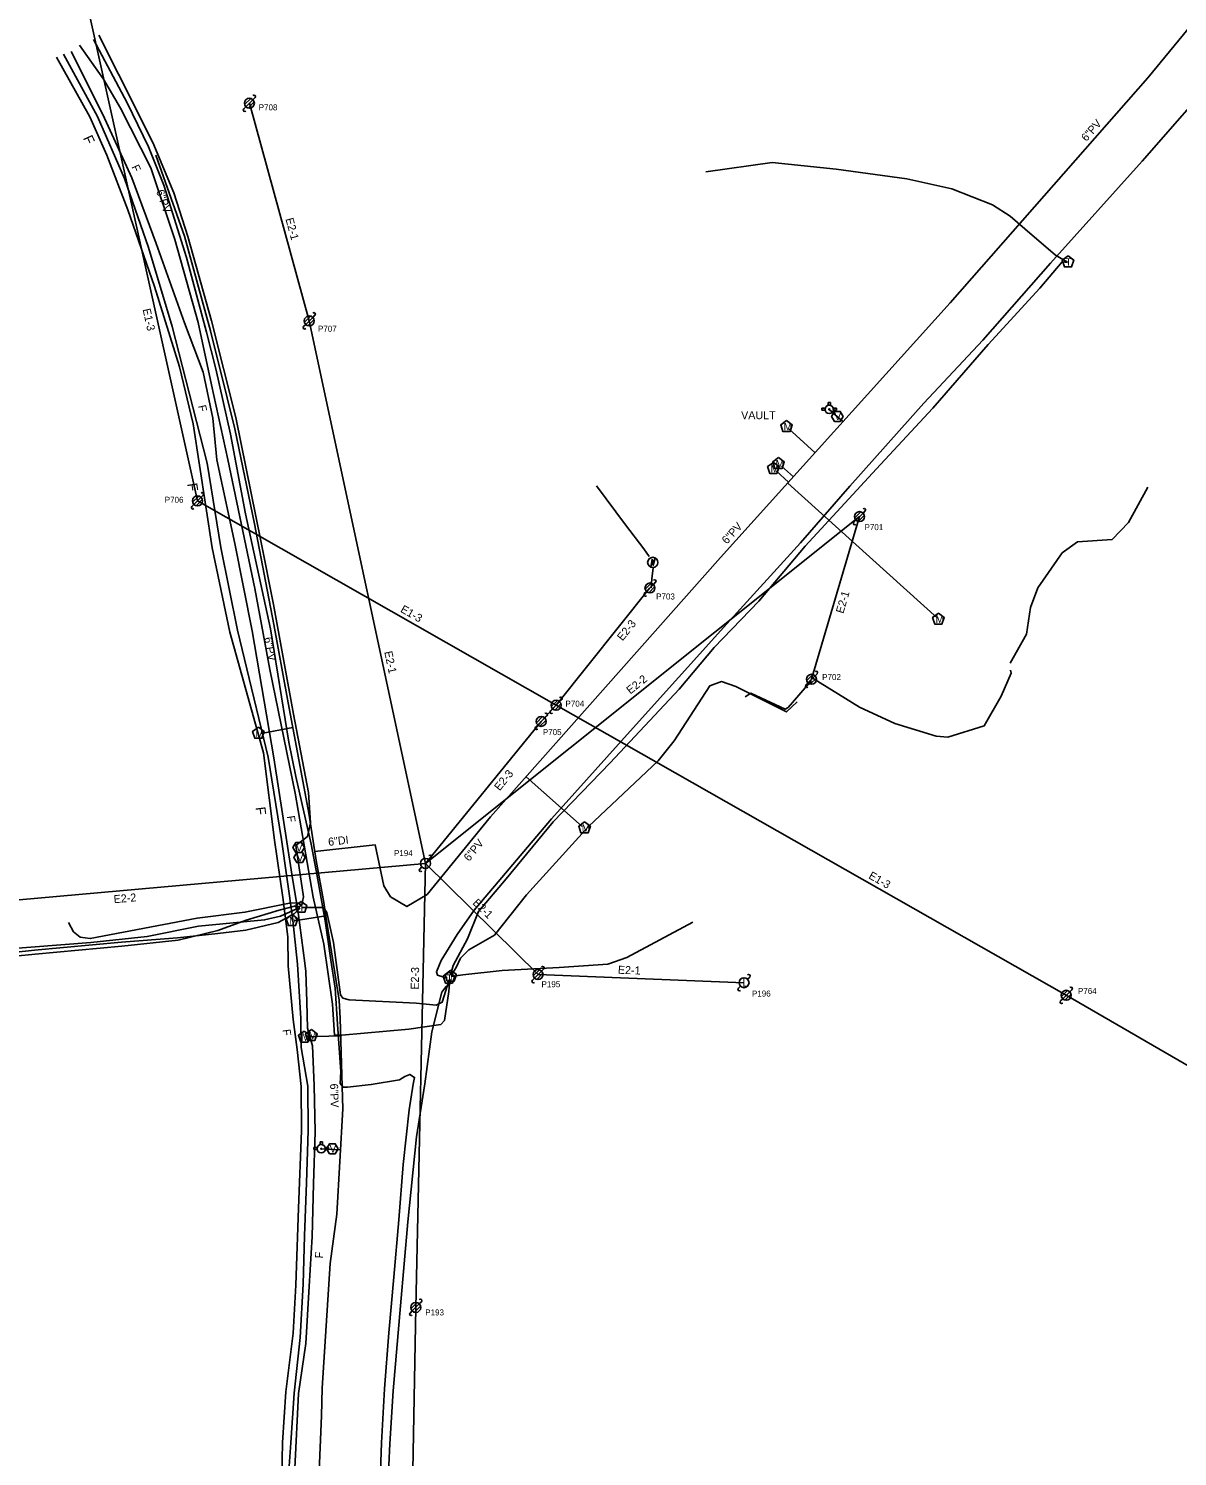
# Model space of a CAD drawing. Extents: x 1614474 to 1865144, y 1098877 to 1212550.
# Drawn here: x 1771883 to 1772457, y 1180446 to 1181160 of the extents above; entities that cross this region are included whole.
import ezdxf

# ---------------------------------------------------------------- set-up
doc = ezdxf.new("R2010")
doc.units = 0
for name, color, linetype in [('RD_EX_SU_Elec', 7, 'Continuous'), ('RD_EX_SU_H2O', 7, 'Continuous'), ('RD_EX_SU_Ovhd', 7, 'Continuous'), ('RD_EX_SU_Pole', 7, 'Continuous'), ('RD_EX_SU_Telecom', 7, 'Continuous'), ('RD_EX_SU_TX_H2O', 7, 'Continuous'), ('RD_EX_SU_TX_Pole', 7, 'Continuous'), ('RD_EX_SU_TX_Telecom', 7, 'Continuous')]:
    doc.layers.add(name, color=color, linetype=linetype)

# ---------------------------------------------------------------- blocks, each defined once
blk = doc.blocks.new('SUE_TPP')
at = {"layer": 'RD_EX_SU_Telecom'}
blk.add_lwpolyline([(0, 3), (-2.85, 0.93), (-1.76, -2.43), (1.76, -2.43), (2.85, 0.93)], close=True, dxfattribs=at)
blk.add_text('T', height=3.75, dxfattribs=at).set_placement((-1.25, -1.88))
blk = doc.blocks.new('SUE_PP')
at = {"layer": 'RD_EX_SU_Pole'}
for p, q in [((-2.41, -0.65), (0.65, 2.41)), ((-1.77, -1.77), (1.77, 1.77)), ((-0.65, -2.41), (2.41, 0.65)), ((1.77, 1.77), (2.83, 2.83)), ((-2.83, -2.83), (-1.77, -1.77))]:
    blk.add_line(p, q, dxfattribs=at)
blk.add_circle((0, 0), 2.5, dxfattribs=at)
for centre, start, end in [((2.3, 3.36), 315, 135), ((-2.3, -3.36), 135, 315)]:
    blk.add_arc(centre, 0.75, start, end, dxfattribs=at)
blk = doc.blocks.new('SUE_WV')
at = {"layer": 'RD_EX_SU_H2O'}
blk.add_lwpolyline([(2.89, 0), (1.44, 2.5), (-1.44, 2.5), (-2.89, 0), (-1.44, -2.5), (1.44, -2.5)], close=True, dxfattribs=at)
blk.add_text('V', height=3.75, dxfattribs=at).set_placement((-1.43, -1.88))
blk = doc.blocks.new('SUE_WFH')
at = {"layer": 'RD_EX_SU_H2O'}
for p, q in [((-2.01, 0.6), (-3.65, 0.6)), ((-3.65, 0.6), (-3.65, -0.45)), ((-0.48, 3.38), (-0.48, 2.04)), ((0.57, 3.38), (-0.48, 3.38)), ((0.57, 2.02), (0.57, 3.38)), ((3.7, 0.6), (2.01, 0.6)), ((3.7, -0.45), (3.7, 0.6)), ((-3.65, -0.45), (-2.05, -0.45)), ((2.05, -0.45), (3.7, -0.45))]:
    blk.add_line(p, q, dxfattribs=at)
for radius in [2.1, 0.263]:
    blk.add_circle((0, 0), radius, dxfattribs=at)
for start, end in [(163.3387, 192.31502), (74.24552, 103.21276), (347.68498, 16.6613)]:
    blk.add_arc((0, 0), 2.1, start, end, dxfattribs=at)
blk = doc.blocks.new('SUE_WM')
at = {"layer": 'RD_EX_SU_H2O'}
blk.add_lwpolyline([(0, 3.05), (-2.9, 0.94), (-1.79, -2.47), (1.79, -2.47), (2.9, 0.94)], close=True, dxfattribs=at)
blk.add_text('M', height=3.75, dxfattribs=at).set_placement((-1.43, -1.88))
blk = doc.blocks.new('SUE_ETM')
at = {"layer": 'RD_EX_SU_Elec'}
blk.add_lwpolyline([(1.24, 2.04), (0.23, -1.41), (-0.27, 0.46), (-1.03, -2.36), (-0.34, 1.55), (0.22, -0.39)], close=True, dxfattribs=at)
blk.add_circle((0, 0), 2.55, dxfattribs=at)

msp = doc.modelspace()

# ---------------------------------------------------------------- linework, layer by layer
at = {"layer": 'RD_EX_SU_Elec'}
for points in [[(1772166.5, 1180930.99), (1772181.07, 1180911.44), (1772190.3, 1180899.42), (1772192.86, 1180895.64)], [(1772193.85, 1180879.93), (1772194.2, 1180884.58), (1772194.89, 1180889.99)], [(1772274.93, 1180834.64), (1772298.08, 1180820.4), (1772315.7, 1180812.13), (1772336.3, 1180805.79), (1772342.21, 1180805.29), (1772360.4, 1180810.98), (1772368.82, 1180825.83), (1772373.82, 1180837.4), (1772373.57, 1180838.8)], [(1772240.86, 1180825.55), (1772243.66, 1180827.4), (1772260.87, 1180819.27), (1772262.4, 1180820.19), (1772274.05, 1180833.69)]]:
    msp.add_lwpolyline(points, dxfattribs=at)
at = {"layer": 'RD_EX_SU_H2O'}
for p, q in [((1772282.91, 1180969.23), (1772289.82, 1180963)), ((1772262.58, 1180959.61), (1772275.92, 1180947.58)), ((1772256.33, 1180938.42), (1772262.58, 1180932.79)), ((1772259.12, 1180940.78), (1772265, 1180935.47)), ((1772262.17, 1180932.33), (1772337.07, 1180864.8)), ((1771998.95, 1180807.18), (1772014.71, 1180810.13)), ((1772131.37, 1180785.58), (1772159.36, 1180760.73)), ((1772015.43, 1180713.54), (1772031.29, 1180716.02)), ((1772021.04, 1180655.5), (1772038.62, 1180656.05)), ((1772028.96, 1180599.58), (1772038.56, 1180599.02))]:
    msp.add_line(p, q, dxfattribs=at)
for points in [[(1772113.57, 1180765.54), (1772228.62, 1180895.12), (1772343.42, 1181022.45), (1772442.26, 1181134.91), (1772535.84, 1181249.02), (1772563.53, 1181288.52), (1772591.62, 1181328.82), (1772640.34, 1181415.41), (1772682.27, 1181505.27), (1772700.74, 1181551.33), (1772738.36, 1181647.58), (1772786.7, 1181777.24)], [(1771946.33, 1181096.31), (1771960.64, 1181055.82), (1771973.6, 1181008.54), (1771976.62, 1180996.3), (1771978.04, 1180990.49), (1771985.75, 1180959.54), (1771995.65, 1180911.92), (1772005.3, 1180861.73), (1772012.04, 1180824.37), (1772022.72, 1180767.33), (1772026.42, 1180743.62), (1772030.32, 1180722.72), (1772031.31, 1180715.87), (1772037.92, 1180673.78), (1772038.35, 1180664.76), (1772039.77, 1180619.55), (1772036.68, 1180566.85), (1772033.48, 1180542.16), (1772029.35, 1180479.91), (1772029.16, 1180466.1), (1772027.05, 1180418.5)], [(1772025.71, 1180748.18), (1772055.84, 1180751.59), (1772060.2, 1180731.07), (1772063.62, 1180725.56), (1772071.79, 1180720.62), (1772081.93, 1180726.7), (1772113.57, 1180765.54)]]:
    msp.add_lwpolyline(points, dxfattribs=at)
at = {"layer": 'RD_EX_SU_Ovhd'}
for p, q in [((1771888.17, 1181278.32), (1771967.08, 1180923.48)), ((1771993.03, 1181122.27), (1772022.97, 1181013.47)), ((1772022.97, 1181013.47), (1772081.03, 1180742.23)), ((1771967.08, 1180923.48), (1772146.37, 1180821.31)), ((1772081.03, 1180742.23), (1772298.04, 1180915.6)), ((1772274.06, 1180834.26), (1772298.04, 1180915.6)), ((1772146.37, 1180821.31), (1772193.3, 1180879.94)), ((1772138.94, 1180813.23), (1772146.37, 1180821.31)), ((1772146.37, 1180821.31), (1772401.4, 1180676.27)), ((1772081.03, 1180742.23), (1772138.94, 1180813.23)), ((1771857.86, 1180722.29), (1772081.03, 1180742.23)), ((1772076.21, 1180520.25), (1772081.03, 1180742.23)), ((1772081.03, 1180742.23), (1772137.34, 1180686.65)), ((1772137.34, 1180686.65), (1772240.32, 1180682.6)), ((1772401.4, 1180676.27), (1772645.63, 1180534.74)), ((1772072.6, 1180312.82), (1772076.21, 1180520.25))]:
    msp.add_line(p, q, dxfattribs=at)
at = {"layer": 'RD_EX_SU_Pole'}
for p, q in [((1772082.8, 1180744), (1772083.86, 1180745.06)), ((1772078.2, 1180739.4), (1772079.26, 1180740.47)), ((1772242.09, 1180684.37), (1772243.15, 1180685.43)), ((1772237.49, 1180679.77), (1772238.55, 1180680.83))]:
    msp.add_line(p, q, dxfattribs=at)
for centre in [(1772081.03, 1180742.23), (1772240.32, 1180682.6)]:
    msp.add_circle(centre, 2.5, dxfattribs=at)
for centre, start, end in [((1772083.33, 1180745.59), 315, 135), ((1772078.73, 1180738.87), 135, 315), ((1772242.62, 1180685.96), 315, 135), ((1772238.02, 1180679.24), 135, 315)]:
    msp.add_arc(centre, 0.75, start, end, dxfattribs=at)
at = {"layer": 'RD_EX_SU_Telecom'}
for points in [[(1772091.89, 1180684.87), (1772087.11, 1180686.29), (1772086.52, 1180688.08), (1772088.93, 1180693.62), (1772096.91, 1180706.61), (1772105.42, 1180718.77), (1772144.04, 1180764.5), (1772183.39, 1180808.36), (1772231.73, 1180862.02), (1772268.62, 1180902.51), (1772293.18, 1180930.86), (1772330.2, 1180972.4), (1772359.62, 1181003.89), (1772393.58, 1181042.3), (1772439.39, 1181093.24), (1772480.57, 1181140.31), (1772507.32, 1181173.35), (1772546.01, 1181222.2), (1772609.98, 1181309.67), (1772659.45, 1181393.41), (1772700.65, 1181486.4), (1772715.32, 1181519.93), (1772719.6, 1181522.19), (1772730.27, 1181518.08)], [(1771917.79, 1181156.28), (1771927.62, 1181136.81), (1771944.74, 1181102.65), (1771955.34, 1181077.57), (1771962.2, 1181055.67), (1771974.12, 1181013.54), (1771986.2, 1180965.12), (1771998.99, 1180902.73), (1772005.01, 1180871.62), (1772015.11, 1180816.88), (1772022.57, 1180777.7), (1772023.66, 1180762.52), (1772022.01, 1180755.61), (1772016.23, 1180751.12), (1772020.05, 1180725.5), (1772019.08, 1180720.83)], [(1771908.05, 1181151.32), (1771920.11, 1181134.3), (1771928.6, 1181119.86), (1771943.75, 1181089.97), (1771955.68, 1181054.1), (1771967.37, 1181012.61), (1771974.13, 1180981.54), (1771982.29, 1180944.2), (1771995.79, 1180879.74), (1772003.33, 1180839.12), (1772015.99, 1180777.28), (1772024.89, 1180725.41), (1772030.2, 1180701.82), (1772034.65, 1180671.88), (1772035.58, 1180656.39), (1772039.28, 1180656.4), (1772072.7, 1180659.3), (1772088.74, 1180661.63), (1772090.58, 1180663.74), (1772092.74, 1180678.15), (1772093.18, 1180684.24)], [(1771915.16, 1181154.11), (1771931.91, 1181122.48), (1771942.63, 1181100.42), (1771950.22, 1181081.36), (1771961.67, 1181045.09), (1771971.58, 1181007.75), (1771976.25, 1180989.42), (1771983.6, 1180956.79), (1771991.09, 1180917.05), (1772003.57, 1180859.55), (1772012.74, 1180802.76), (1772016.33, 1180785.64), (1772023.87, 1180751.91), (1772026.38, 1180738.65), (1772030.93, 1180713.46), (1772033.7, 1180693.82)], [(1771896.64, 1181145.31), (1771913.21, 1181115.46), (1771921.78, 1181096.31), (1771932.3, 1181069.05), (1771945.56, 1181030.61), (1771958.05, 1180990.5), (1771964.87, 1180962.01), (1771974.5, 1180899.94), (1771983.32, 1180857.86), (1772000.11, 1180797.46), (1772005.64, 1180753.88), (1772009.8, 1180725.1), (1772012.18, 1180705.59), (1772012.4, 1180691.05)], [(1771900.06, 1181146.75), (1771917.14, 1181115.59), (1771930.6, 1181084.73), (1771942.57, 1181050.14), (1771954.42, 1181010.69), (1771961.18, 1180983.97), (1771971.88, 1180942.27), (1771978.71, 1180900.18), (1771987.08, 1180858.9), (1772002.34, 1180795.39), (1772009.12, 1180754.22), (1772014.54, 1180715.3), (1772017.04, 1180691.88)], [(1771903.86, 1181148.19), (1771919.84, 1181116.73), (1771934.24, 1181085.07), (1771946.42, 1181052.14), (1771960.63, 1181012.55), (1771969.87, 1180987.89), (1771974.81, 1180964.86), (1771976.79, 1180943.99), (1771985.8, 1180902.22), (1771994.39, 1180858.54), (1772005.26, 1180794.94), (1772014.19, 1180736.79), (1772017.43, 1180717.74), (1772020.81, 1180692.29)], [(1772221.21, 1181088), (1772254.32, 1181092.62), (1772286.36, 1181089.39), (1772321.68, 1181084.55), (1772344.19, 1181079.54), (1772364.57, 1181071.5), (1772373.36, 1181065.87), (1772380.63, 1181059.54), (1772396.07, 1181046.28), (1772402, 1181042.87)], [(1772093.53, 1180686.4), (1772094.89, 1180691.23), (1772102.07, 1180704.55), (1772107.6, 1180718.14), (1772121.36, 1180734.51), (1772144.84, 1180762.93), (1772173.47, 1180792.57), (1772207.87, 1180829.31), (1772225.42, 1180850.1), (1772247.74, 1180873.29), (1772270.81, 1180900.83), (1772308.54, 1180941.66), (1772334.71, 1180969.75), (1772362.3, 1181001.58), (1772388.25, 1181029.81), (1772399.37, 1181042.95), (1772402.07, 1181042.65)], [(1772373.31, 1180842.38), (1772381.59, 1180856.87), (1772383.57, 1180870.15), (1772387.14, 1180880.03), (1772399.39, 1180897.42), (1772406.97, 1180902.93), (1772424.29, 1180904.12), (1772432.57, 1180912.64), (1772442.18, 1180930.39)], [(1772205.44, 1180803.45), (1772223.14, 1180831.08), (1772229.1, 1180833.17), (1772236.2, 1180830.61)], [(1772236.2, 1180830.61), (1772261.47, 1180817.97), (1772266.82, 1180823)], [(1772093.86, 1180686.12), (1772096.37, 1180690.13), (1772098.61, 1180694.9), (1772102.73, 1180698.99), (1772115.54, 1180706.34), (1772131.63, 1180726.5), (1772162.62, 1180760.61), (1772197.35, 1180793.53), (1772205.44, 1180803.45)], [(1771587.15, 1180459.73), (1771589.21, 1180479.94), (1771594.54, 1180498.57), (1771604.64, 1180518.89), (1771620.34, 1180538.47), (1771644.7, 1180562.03), (1771656.29, 1180575.92), (1771676.28, 1180601.07), (1771696.75, 1180642.18), (1771715.12, 1180663.08), (1771734.81, 1180675.7), (1771753.58, 1180681.9), (1771803.62, 1180689.32), (1771855.23, 1180693.88), (1771885.92, 1180696.78), (1771929.22, 1180700.82), (1771957.5, 1180703.88), (1771977.31, 1180708.74), (1771991.43, 1180713.91), (1772007.96, 1180718.9), (1772016.21, 1180721.06), (1772018.22, 1180720.58)], [(1771902.53, 1180712.76), (1771905.04, 1180708.04), (1771908.37, 1180705.41), (1771913.45, 1180704.61), (1771966.87, 1180714.89), (1771990.79, 1180717.81), (1772013.01, 1180722.35), (1772017.99, 1180722.57), (1772018.74, 1180720.65)], [(1771673.08, 1180710.15), (1771725.33, 1180692.64), (1771754.29, 1180689.69), (1771834.8, 1180695.43), (1771868.85, 1180699.19), (1771913.8, 1180702.63), (1771941.97, 1180705.7), (1771967.65, 1180710.79), (1772000.6, 1180714.01), (1772008.52, 1180715.93), (1772018.24, 1180720.18)], [(1771753.67, 1180682.97), (1771803.71, 1180690.91), (1771855, 1180695.57), (1771885.61, 1180698.79), (1771929.06, 1180702.84), (1771957.15, 1180705.08), (1771977.25, 1180707.15), (1771991.28, 1180708.86), (1772007.5, 1180712.7), (1772015.5, 1180717.03), (1772018.36, 1180719.84)], [(1772019.19, 1180720.22), (1772030.14, 1180720.2), (1772031.68, 1180717.6), (1772035.13, 1180702.65), (1772038.63, 1180676.45), (1772039.76, 1180674.77), (1772042.85, 1180673.95), (1772076.4, 1180672.36), (1772086.4, 1180671.38), (1772089.48, 1180672.86), (1772092.89, 1180684.05)], [(1772093.9, 1180685.69), (1772099.69, 1180686.56), (1772119.43, 1180688.61), (1772147.97, 1180690.23), (1772172.18, 1180691.83), (1772181.77, 1180695.17), (1772214.8, 1180712.82)], [(1772020.81, 1180692.29), (1772021.27, 1180688.23), (1772021.68, 1180672.96), (1772022.14, 1180659.78), (1772024.54, 1180651), (1772025.43, 1180631.15), (1772025.9, 1180608.06), (1772025.16, 1180581.97), (1772024.46, 1180555.62), (1772022.98, 1180530.76), (1772021.28, 1180502.21), (1772017.52, 1180477.19), (1772015.73, 1180439.92), (1772014.84, 1180427.29), (1772013.76, 1180386.43), (1772012.51, 1180360.39), (1772013.33, 1180334.64), (1772013.48, 1180321.01), (1772015.66, 1180295.14), (1772017.49, 1180268.59), (1772019.54, 1180245.54), (1772022.98, 1180205.51), (1772023.89, 1180198.24), (1772026.76, 1180190.86)], [(1772033.7, 1180693.82), (1772035.89, 1180679.86), (1772037.12, 1180661.79), (1772038.81, 1180638.02), (1772038.35, 1180632.14), (1772039.93, 1180630.4), (1772042.16, 1180630.28), (1772053.92, 1180631.61), (1772068.02, 1180634.1), (1772070.78, 1180635.65), (1772073.19, 1180636.71), (1772075.59, 1180635.24), (1772074.94, 1180631.81), (1772072.94, 1180619.04), (1772069.95, 1180591.63), (1772067.71, 1180563.97), (1772065.31, 1180535.43), (1772062.67, 1180507.57), (1772060.59, 1180479.54), (1772059.04, 1180452.51), (1772058.05, 1180424.17)], [(1772012.4, 1180691.05), (1772014.96, 1180664.17), (1772016.98, 1180649.27), (1772018.9, 1180630.77), (1772019.09, 1180608.47), (1772017.52, 1180569.82), (1772016.3, 1180531.32), (1772014.96, 1180507.29), (1772011.23, 1180478.08), (1772009.64, 1180452.63), (1772008.51, 1180400.68), (1772008.17, 1180360.43), (1772009.54, 1180320.86), (1772012.41, 1180281.05), (1772014.97, 1180244.87), (1772018.85, 1180205.33), (1772021.16, 1180180.29), (1772026.12, 1180158.87), (1772029.53, 1180133.75), (1772032.05, 1180118.67), (1772034.35, 1180108.62), (1772035.86, 1180102.65)], [(1772017.04, 1180691.88), (1772018.72, 1180664.67), (1772018.85, 1180650.21), (1772022.23, 1180630.88), (1772022.45, 1180608.65), (1772021.66, 1180582.51), (1772020.66, 1180556.08), (1772020, 1180531.89), (1772018.46, 1180505.27), (1772015.48, 1180477.33), (1772013.83, 1180452.5), (1772011.97, 1180426.89)], [(1772093.26, 1180684.17), (1772093.78, 1180683.39), (1772093.38, 1180682.04), (1772091.18, 1180680.53), (1772089.29, 1180677.82), (1772084.23, 1180658.05), (1772080.74, 1180632.02), (1772076.55, 1180605.53), (1772072.26, 1180563.1), (1772068.53, 1180520.99), (1772064.99, 1180478.55), (1772063.24, 1180452.07), (1772061.27, 1180409.29), (1772060.04, 1180368.49), (1772059.73, 1180343.81), (1772059.04, 1180317.82), (1772061.04, 1180294.69), (1772063.08, 1180269.32), (1772066.45, 1180228.96), (1772069.24, 1180201.17), (1772075.4, 1180171.53)]]:
    msp.add_lwpolyline(points, dxfattribs=at)

# ---------------------------------------------------------------- block references
at = {"layer": 'RD_EX_SU_Elec'}
msp.add_blockref('SUE_ETM', (1772194.69, 1180892.73), dxfattribs=at)
at = {"layer": 'RD_EX_SU_H2O'}
for name, p in [('SUE_WFH', (1772282.91, 1180969.23)), ('SUE_WM', (1772261.55, 1180960.56)), ('SUE_WV', (1772286.95, 1180965.74)), ('SUE_WM', (1772255, 1180939.66)), ('SUE_WM', (1772257.55, 1180942.1)), ('SUE_WM', (1772337.48, 1180864.31)), ('SUE_WM', (1771997.51, 1180807.27)), ('SUE_WM', (1772160.59, 1180759.9)), ('SUE_WV', (1772017.69, 1180750.1)), ('SUE_WV', (1772018.11, 1180745.12)), ('SUE_WM', (1772014.35, 1180713.63)), ('SUE_WM', (1772020.47, 1180655.38)), ('SUE_WM', (1772024.02, 1180656.16)), ('SUE_WFH', (1772028.96, 1180599.58)), ('SUE_WV', (1772034.54, 1180599.56))]:
    msp.add_blockref(name, p, dxfattribs=at)
at = {"layer": 'RD_EX_SU_Pole'}
for p in [(1771993.03, 1181122.27), (1772022.97, 1181013.47), (1771967.08, 1180923.48), (1772298.04, 1180915.6), (1772193.3, 1180879.94), (1772274.06, 1180834.26), (1772146.37, 1180821.31), (1772138.94, 1180813.23), (1772137.34, 1180686.65), (1772401.4, 1180676.27), (1772076.21, 1180520.25)]:
    msp.add_blockref('SUE_PP', p, dxfattribs=at)
at = {"layer": 'RD_EX_SU_Telecom'}
for p in [(1772402.28, 1181042.91), (1772018.91, 1180720.25), (1772092.81, 1180684.85), (1772093.71, 1180685.81)]:
    msp.add_blockref('SUE_TPP', p, dxfattribs=at)

# ---------------------------------------------------------------- texts
at = {"layer": 'RD_EX_SU_Ovhd'}
for s, rotation, p in [('E2-1', 285.3879, (1772011.03, 1181064.39)), ('E1-3', 282.53643, (1771939.64, 1181019.21)), ('E2-1', 73.57466, (1772289.94, 1180866.9)), ('E1-3', 330.32481, (1772068.21, 1180868.16)), ('E2-3', 51.3239, (1772179.57, 1180853.18)), ('E2-1', 282.0816, (1772060.45, 1180847.93)), ('E2-2', 38.62203, (1772183.48, 1180826.64)), ('E2-3', 50.79608, (1772118.14, 1180778.23)), ('E1-3', 330.37183, (1772302.25, 1180734.96)), ('E2-2', 5.10586, (1771925.37, 1180722.3)), ('E2-1', 315.37285, (1772104.38, 1180722.19)), ('E2-3', 88.75443, (1772077.66, 1180679.07)), ('E2-1', 357.74565, (1772177.21, 1180687.09))]:
    msp.add_text(s, height=4, rotation=rotation, dxfattribs=at).set_placement(p)
at = {"layer": 'RD_EX_SU_Pole'}
for p in [(1772080.17, 1180740.23), (1772239.46, 1180680.6)]:
    msp.add_text('L', height=4, dxfattribs=at).set_placement(p)
at = {"layer": 'RD_EX_SU_TX_H2O'}
for s, rotation, p in [('6"PV', 48.68816, (1772411.46, 1181102.9)), ('6"PV', 289.46453, (1771946.33, 1181078.3)), ('6"PV', 47.96221, (1772231.74, 1180901.57)), ('6"PV', 280.22723, (1772000.42, 1180855.02)), ('6"DI', 6.44276, (1772032.64, 1180750.98)), ('6"PV', 50.82834, (1772102.9, 1180742.94)), ('6"PV', 271.79264, (1772033.37, 1180632.1))]:
    msp.add_text(s, height=4, rotation=rotation, dxfattribs=at).set_placement(p)
msp.add_text('VAULT', height=4, dxfattribs=at).set_placement((1772238.87, 1180964.33))
at = {"layer": 'RD_EX_SU_TX_Pole'}
for s, p in [('P708', (1771997.69, 1181118.72)), ('P707', (1772027.32, 1181008.04)), ('P706', (1771950.72, 1180922.52)), ('P701', (1772300.56, 1180908.84)), ('P703', (1772196.37, 1180874.18)), ('P702', (1772279.38, 1180833.88)), ('P704', (1772151.06, 1180820.59)), ('P705', (1772139.74, 1180806.37)), ('P194', (1772065.32, 1180745.87)), ('P195', (1772139.07, 1180680.33)), ('P196', (1772244.28, 1180675.66)), ('P764', (1772407.26, 1180676.93)), ('P193', (1772080.95, 1180516.23))]:
    msp.add_text(s, height=3, dxfattribs=at).set_placement(p)
at = {"layer": 'RD_EX_SU_TX_Telecom'}
for height, rotation, p in [(5, 294.11623, (1771909.72, 1181104.89)), (4, 294.45477, (1771933.98, 1181090.46)), (4, 282.09454, (1771967.36, 1180970.97)), (5, 278.81471, (1771961.93, 1180932.02)), (5, 277.23812, (1771996.01, 1180770.2)), (4, 278.72776, (1772011.76, 1180765.78)), (4, 277.70308, (1772009.6, 1180659.08)), (4, 86.59267, (1772029.82, 1180544.69))]:
    msp.add_text('F', height=height, rotation=rotation, dxfattribs=at).set_placement(p)

doc.saveas('drawing.dxf')
